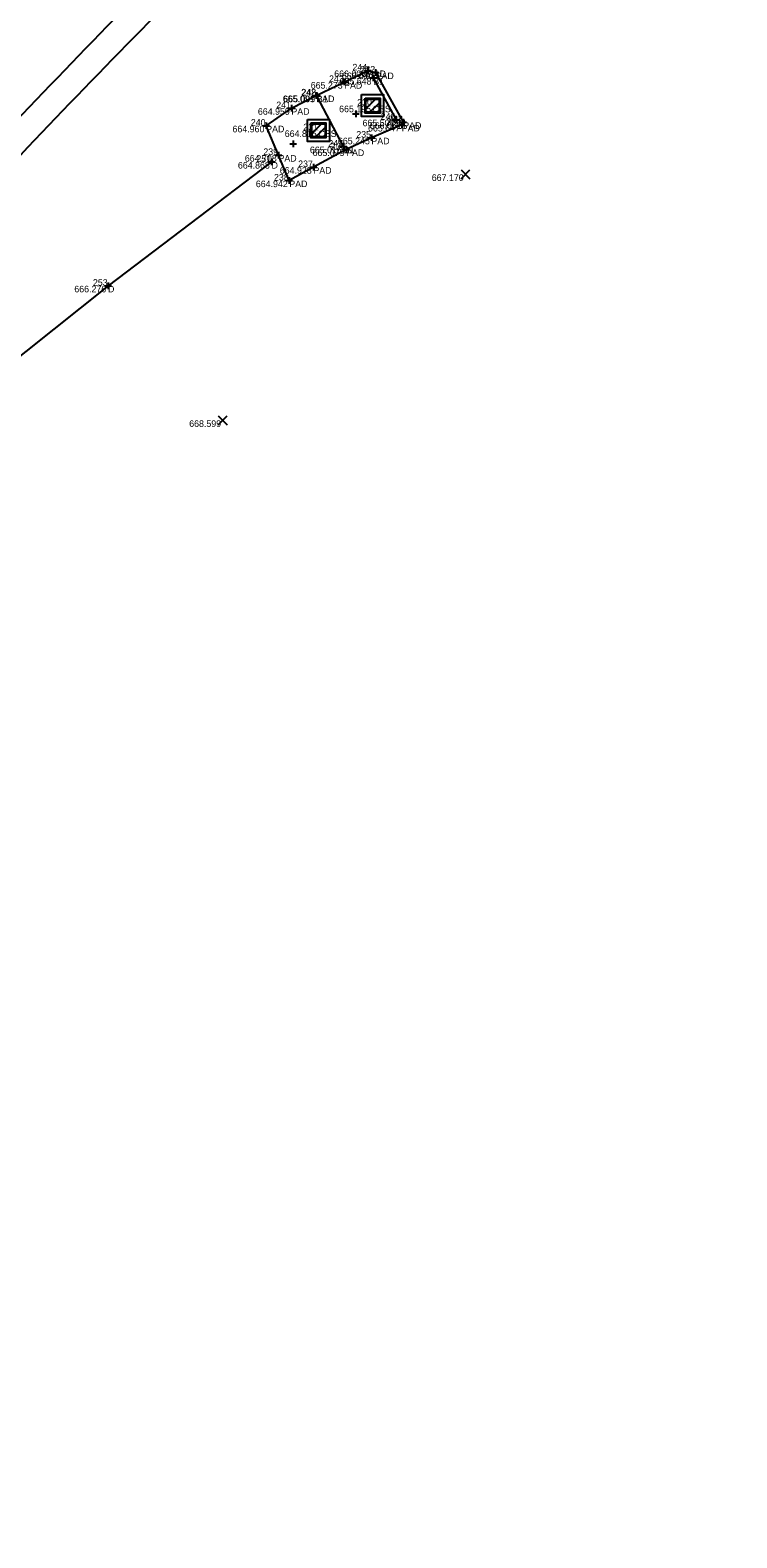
# Model space of a CAD drawing. Extents: x 2197382 to 2204062, y 634117 to 636522.
# Drawn here: x 2202463.8 to 2202570.9, y 634830.5 to 635059.1 of the extents above; entities that cross this region are included whole.
import ezdxf

# ---------------------------------------------------------------- set-up
doc = ezdxf.new("R2010")
doc.units = 0
for name, color, linetype in [('_CIVIL_CONSTRUCTION', 7, 'Continuous'), ('BR_P_Gen_Approach_Slab', 7, 'Continuous'), ('DR_X_Ditch', 7, 'Continuous'), ('GE_P_Alignment', 7, 'Continuous'), ('GE_P_Alignment_100_Cardinal_Points', 7, 'Continuous'), ('GE_P_Alignment_100_Distances', 7, 'Continuous'), ('GE_X_Alignment', 7, 'Continuous'), ('RW_X_CL_100_Curve_Data', 7, 'Continuous'), ('SH_Border', 7, 'Continuous'), ('SH_Cut_Line', 7, 'Continuous'), ('SH_Data', 7, 'Continuous'), ('SH_Text', 7, 'Continuous')]:
    doc.layers.add(name, color=color, linetype=linetype)

msp = doc.modelspace()

# ---------------------------------------------------------------- linework, layer by layer
at = {"layer": '_CIVIL_CONSTRUCTION'}
for p, q in [((2202510.91, 635051.21), (2202511.91, 635051.21)), ((2202511.41, 635051.71), (2202511.41, 635050.71)), ((2202511.41, 635051.21), (2202511.41, 635051.21)), ((2202514.51, 635052.96), (2202515.51, 635052.96)), ((2202515.01, 635053.46), (2202515.01, 635052.46)), ((2202515.01, 635052.96), (2202515.01, 635052.96)), ((2202515.32, 635051.82), (2202516.32, 635051.82)), ((2202515.68, 635052.65), (2202516.68, 635052.65)), ((2202515.82, 635052.32), (2202515.82, 635051.32)), ((2202515.82, 635051.82), (2202515.82, 635051.82)), ((2202516.18, 635053.15), (2202516.18, 635052.15)), ((2202516.18, 635052.65), (2202516.18, 635052.65)), ((2202506.69, 635049.17), (2202507.69, 635049.17)), ((2202506.77, 635049.14), (2202507.77, 635049.14)), ((2202507.19, 635049.67), (2202507.19, 635048.67)), ((2202507.19, 635049.17), (2202507.19, 635049.17)), ((2202507.27, 635049.64), (2202507.27, 635048.64)), ((2202507.27, 635049.14), (2202507.27, 635049.14)), ((2202502.92, 635047.24), (2202503.92, 635047.24)), ((2202503.42, 635047.74), (2202503.42, 635046.74)), ((2202503.42, 635047.24), (2202503.42, 635047.24)), ((2202513.2, 635046.88), (2202513.2, 635045.88)), ((2202499.1, 635044.59), (2202500.1, 635044.59)), ((2202499.6, 635045.09), (2202499.6, 635044.09)), ((2202499.6, 635044.59), (2202499.6, 635044.59)), ((2202512.7, 635046.38), (2202513.7, 635046.38)), ((2202513.2, 635046.38), (2202513.2, 635046.38)), ((2202518.78, 635045.5), (2202519.78, 635045.5)), ((2202519.28, 635046), (2202519.28, 635045)), ((2202519.28, 635045.5), (2202519.28, 635045.5)), ((2202519.63, 635044.71), (2202520.63, 635044.71)), ((2202519.87, 635045.11), (2202520.87, 635045.11)), ((2202520.13, 635045.21), (2202520.13, 635044.21)), ((2202520.13, 635044.71), (2202520.13, 635044.71)), ((2202520.37, 635045.61), (2202520.37, 635044.61)), ((2202520.37, 635045.11), (2202520.37, 635045.11)), ((2202503.69, 635042.32), (2202503.69, 635041.32)), ((2202515.04, 635042.77), (2202516.04, 635042.77)), ((2202515.54, 635043.27), (2202515.54, 635042.27)), ((2202515.54, 635042.77), (2202515.54, 635042.77)), ((2202500.96, 635040.14), (2202501.96, 635040.14)), ((2202501.46, 635040.64), (2202501.46, 635039.64)), ((2202501.46, 635040.14), (2202501.46, 635040.14)), ((2202503.19, 635041.82), (2202504.19, 635041.82)), ((2202503.69, 635041.82), (2202503.69, 635041.82)), ((2202510.83, 635041.42), (2202511.83, 635041.42)), ((2202511.21, 635040.99), (2202512.21, 635040.99)), ((2202511.33, 635041.92), (2202511.33, 635040.92)), ((2202511.33, 635041.42), (2202511.33, 635041.42)), ((2202511.71, 635041.49), (2202511.71, 635040.49)), ((2202511.71, 635040.99), (2202511.71, 635040.99)), ((2202499.91, 635039.09), (2202500.91, 635039.09)), ((2202500.41, 635039.59), (2202500.41, 635038.59)), ((2202500.41, 635039.09), (2202500.41, 635039.09)), ((2202506.26, 635038.31), (2202507.26, 635038.31)), ((2202506.76, 635038.81), (2202506.76, 635037.81)), ((2202506.76, 635038.31), (2202506.76, 635038.31)), ((2202502.6, 635036.27), (2202503.6, 635036.27)), ((2202503.1, 635036.77), (2202503.1, 635035.77)), ((2202503.1, 635036.27), (2202503.1, 635036.27)), ((2202475.13, 635020.32), (2202476.13, 635020.32)), ((2202475.63, 635020.82), (2202475.63, 635019.82)), ((2202475.63, 635020.32), (2202475.63, 635020.32))]:
    msp.add_line(p, q, dxfattribs=at)
at = {"layer": 'BR_P_Gen_Approach_Slab'}
msp.add_lwpolyline([(2202516.18, 635052.65), (2202520.37, 635045.11), (2202520.13, 635044.71), (2202515.54, 635042.77), (2202511.71, 635040.99), (2202506.76, 635038.31), (2202503.1, 635036.27), (2202501.46, 635040.14), (2202499.6, 635044.59), (2202503.42, 635047.24), (2202507.19, 635049.17), (2202511.41, 635051.21), (2202515.01, 635052.96)], close=True, dxfattribs=at)
at = {"layer": 'DR_X_Ditch'}
msp.add_lwpolyline([(2202500.41, 635039.09), (2202475.63, 635020.32), (2202434.18, 634987.28), (2202402.81, 634952.88), (2202370.81, 634914.73), (2202342.37, 634876.16), (2202312.08, 634836.04), (2202284.91, 634798.23), (2202254.23, 634756.84), (2202226.56, 634714.46), (2202198.47, 634675.43), (2202174.83, 634632.13), (2202164.13, 634613.64)], dxfattribs=at)
at = {"layer": 'GE_P_Alignment'}
for p, q in [((2202514.58, 635047.02), (2202516.33, 635048.77)), ((2202514.58, 635048.15), (2202515.2, 635048.77)), ((2202515.17, 635046.48), (2202516.87, 635048.18)), ((2202516.31, 635046.48), (2202516.87, 635047.04)), ((2202506.37, 635043.26), (2202508.13, 635045.02)), ((2202506.37, 635044.4), (2202507, 635045.02)), ((2202506.97, 635042.73), (2202508.66, 635044.42)), ((2202508.1, 635042.73), (2202508.66, 635043.29))]:
    msp.add_line(p, q, dxfattribs=at)
for points in [[(2202514.05, 635049.3), (2202517.39, 635049.3), (2202517.39, 635045.96), (2202514.05, 635045.96)], [(2202514.58, 635048.77), (2202516.87, 635048.77), (2202516.87, 635046.48), (2202514.58, 635046.48)], [(2202514.72, 635048.63), (2202516.72, 635048.63), (2202516.72, 635046.63), (2202514.72, 635046.63)], [(2202505.85, 635045.54), (2202509.18, 635045.54), (2202509.18, 635042.21), (2202505.85, 635042.21)], [(2202506.37, 635045.02), (2202508.66, 635045.02), (2202508.66, 635042.73), (2202506.37, 635042.73)], [(2202506.51, 635044.88), (2202508.51, 635044.88), (2202508.51, 635042.88), (2202506.51, 635042.88)]]:
    msp.add_lwpolyline(points, close=True, dxfattribs=at)
at = {"layer": 'GE_P_Alignment_100_Cardinal_Points'}
for p, q in [((2202515.72, 635049.3), (2202515.72, 635049.3)), ((2202514.72, 635047.63), (2202514.72, 635047.63)), ((2202515.72, 635048.63), (2202515.72, 635048.63)), ((2202515.72, 635047.63), (2202515.72, 635047.63)), ((2202515.72, 635047.63), (2202515.72, 635047.63)), ((2202515.72, 635047.63), (2202515.72, 635047.63)), ((2202516.72, 635047.63), (2202516.72, 635047.63)), ((2202507.51, 635045.54), (2202507.51, 635045.54)), ((2202507.51, 635044.88), (2202507.51, 635044.88)), ((2202515.72, 635046.63), (2202515.72, 635046.63)), ((2202515.72, 635045.96), (2202515.72, 635045.96)), ((2202506.51, 635043.88), (2202506.51, 635043.88)), ((2202507.51, 635043.88), (2202507.51, 635043.88)), ((2202507.51, 635043.88), (2202507.51, 635043.88)), ((2202507.51, 635043.88), (2202507.51, 635043.88)), ((2202507.51, 635042.88), (2202507.51, 635042.88)), ((2202507.51, 635042.21), (2202507.51, 635042.21)), ((2202508.51, 635043.88), (2202508.51, 635043.88))]:
    msp.add_line(p, q, dxfattribs=at)
at = {"layer": 'GE_P_Alignment_100_Distances'}
for points in [[(2202514.19, 635120), (2202501.95, 635108.79), (2202477.63, 635085.87), (2202443.41, 635049.36), (2202409.55, 635012.34), (2202376.26, 634974.99), (2202344.34, 634936.42), (2202312.72, 634897.79), (2202282.43, 634858.12), (2202252.58, 634818.18), (2202223.74, 634777.45), (2202196.69, 634735.5), (2202169.8, 634693.41), (2202144.64, 634650.36), (2202119.18, 634607.44), (2202097.03, 634562.79), (2202074.71, 634518.18), (2202053.15, 634473.28), (2202032.85, 634427.72), (2202013.67, 634381.72), (2201995.41, 634335.21), (2201979.19, 634288.02), (2201963.55, 634240.68), (2201953.92, 634208.98), (2201949.13, 634193.1)], [(2202525.02, 635108.11), (2202513.04, 635097.11), (2202489.33, 635074.07), (2202455.07, 635038.62), (2202421.29, 635002.1), (2202388.81, 634964.35), (2202356.35, 634926.75), (2202325.87, 634887.43), (2202295, 634848.95), (2202265.53, 634808.92), (2202237.35, 634768.89), (2202211.52, 634726.54), (2202183.6, 634685.47), (2202158.14, 634642.34), (2202133.69, 634599.43), (2202111.05, 634555.42), (2202088.76, 634511.33), (2202068.04, 634466.33), (2202047.21, 634421.56), (2202027.88, 634376.06), (2202010.16, 634329.7), (2201994.09, 634282.81), (2201978.74, 634235.43), (2201968.75, 634203.87), (2201963.85, 634187.95)]]:
    msp.add_open_spline(points, degree=3, dxfattribs=at)
at = {"layer": 'GE_X_Alignment'}
for points in [[(2202540.06, 635152.93), (2202529.43, 635144.25), (2202507.23, 635123.46), (2202471.72, 635092.05), (2202435.62, 635056.76), (2202402.1, 635018.87), (2202368.73, 634981.48), (2202336.15, 634943.25), (2202304.62, 634904.21), (2202274.11, 634864.33), (2202244.37, 634823.83), (2202215.65, 634782.83), (2202187.65, 634741.05), (2202161.54, 634698.56), (2202134.84, 634656), (2202111.41, 634611.66), (2202087.71, 634567.52), (2202064.97, 634523.35), (2202044.2, 634477.97), (2202023.42, 634432.25), (2202003.66, 634386.18), (2201990.91, 634355.55), (2201984.79, 634340.33)], [(2202570.92, 635145.14), (2202556.1, 635132.41), (2202530.6, 635107.02), (2202492.19, 635071.28), (2202457.98, 635035.82), (2202424.73, 634999.38), (2202391.64, 634962.22), (2202359.56, 634924.46), (2202328.32, 634885.6), (2202298.37, 634846.53), (2202268.85, 634806.21), (2202240.94, 634765.59), (2202212.91, 634724.71), (2202187.2, 634682.69), (2202161.14, 634640.35), (2202137.99, 634596.95), (2202114.64, 634553.56), (2202092.28, 634509.95), (2202071.73, 634464.7), (2202050.81, 634420.11), (2202031.84, 634374.34), (2202014.23, 634328.21), (2201997.98, 634281.03), (2201983.22, 634233.69), (2201972.74, 634202.38), (2201968.03, 634186.79)]]:
    msp.add_open_spline(points, degree=3, dxfattribs=at)
at = {"layer": 'RW_X_CL_100_Curve_Data'}
for p, q in [((2202529.14, 635036.54), (2202530.47, 635037.88)), ((2202529.14, 635037.88), (2202530.47, 635036.54)), ((2202492.34, 634999.26), (2202493.68, 635000.59)), ((2202492.34, 635000.59), (2202493.68, 634999.26))]:
    msp.add_line(p, q, dxfattribs=at)
at = {"layer": 'SH_Text'}
for points in [[(2202515.82, 635051.82), (2202519.28, 635045.5)], [(2202511.33, 635041.42), (2202507.27, 635049.14)]]:
    msp.add_lwpolyline(points, dxfattribs=at)

# ---------------------------------------------------------------- texts
at = {"layer": 'SH_Border'}
for s, p in [('PAD', (2202511.41, 635050.21)), ('PAD', (2202515.01, 635051.96)), ('B1', (2202515.82, 635050.82)), ('PAD', (2202516.18, 635051.65)), ('PAD', (2202507.19, 635048.17)), ('B1', (2202507.27, 635048.14)), ('PAD', (2202503.42, 635046.24)), ('CBS', (2202515.72, 635046.63)), ('PAD', (2202499.6, 635043.59)), ('B1', (2202519.28, 635044.5)), ('PAD', (2202520.13, 635043.71)), ('PAD', (2202520.37, 635044.11)), ('CBS', (2202507.51, 635042.88)), ('PAD', (2202515.54, 635041.77)), ('PAD', (2202501.46, 635039.14)), ('B1', (2202511.33, 635040.42)), ('PAD', (2202511.71, 635039.99)), ('D', (2202500.41, 635038.09)), ('PAD', (2202506.76, 635037.31)), ('PAD', (2202503.1, 635035.27)), ('D', (2202475.63, 635019.32))]:
    msp.add_text(s, height=1, dxfattribs=at).set_placement(p)
at = {"layer": 'SH_Cut_Line'}
for s, p in [('244', (2202512.67, 635052.96)), ('232', (2202513.88, 635052.65)), ('243', (2202509.12, 635051.21)), ('245', (2202513.53, 635051.82)), ('242', (2202504.9, 635049.17)), ('248', (2202504.95, 635049.14)), ('241', (2202501.12, 635047.24)), ('230', (2202513.39, 635047.63)), ('240', (2202497.27, 635044.59)), ('231', (2202505.21, 635043.88)), ('246', (2202516.95, 635045.5)), ('234', (2202517.79, 635044.71)), ('233', (2202518.09, 635045.11)), ('247', (2202509.01, 635041.42)), ('235', (2202513.25, 635042.77)), ('251', (2202498.11, 635039.09)), ('239', (2202499.16, 635040.14)), ('236', (2202509.39, 635040.99)), ('237', (2202504.44, 635038.31)), ('238', (2202500.78, 635036.27)), ('253', (2202473.34, 635020.32))]:
    msp.add_text(s, height=1, dxfattribs=at).set_placement(p)
at = {"layer": 'SH_Data'}
for s, p in [('665.273', (2202506.35, 635050.21)), ('666.006', (2202509.91, 635051.96)), ('665.648', (2202510.72, 635050.82)), ('666.030', (2202511.06, 635051.65)), ('665.091', (2202502.11, 635048.17)), ('665.099', (2202502.19, 635048.14)), ('664.959', (2202498.34, 635046.24)), ('665.195', (2202510.65, 635046.63)), ('664.960', (2202494.49, 635043.59)), ('665.501', (2202514.2, 635044.5)), ('665.647', (2202515.03, 635043.71)), ('666.061', (2202515.29, 635044.11)), ('664.816', (2202502.41, 635042.88)), ('665.245', (2202510.47, 635041.77)), ('664.708', (2202496.36, 635039.14)), ('665.016', (2202506.22, 635040.42)), ('665.079', (2202506.63, 635039.99)), ('664.868', (2202495.31, 635038.09)), ('664.928', (2202501.66, 635037.31)), ('664.942', (2202498.03, 635035.27)), ('667.170', (2202524.69, 635036.21)), ('666.276', (2202470.52, 635019.32)), ('668.599', (2202487.93, 634998.92))]:
    msp.add_text(s, height=1, dxfattribs=at).set_placement(p)

doc.saveas('drawing.dxf')
